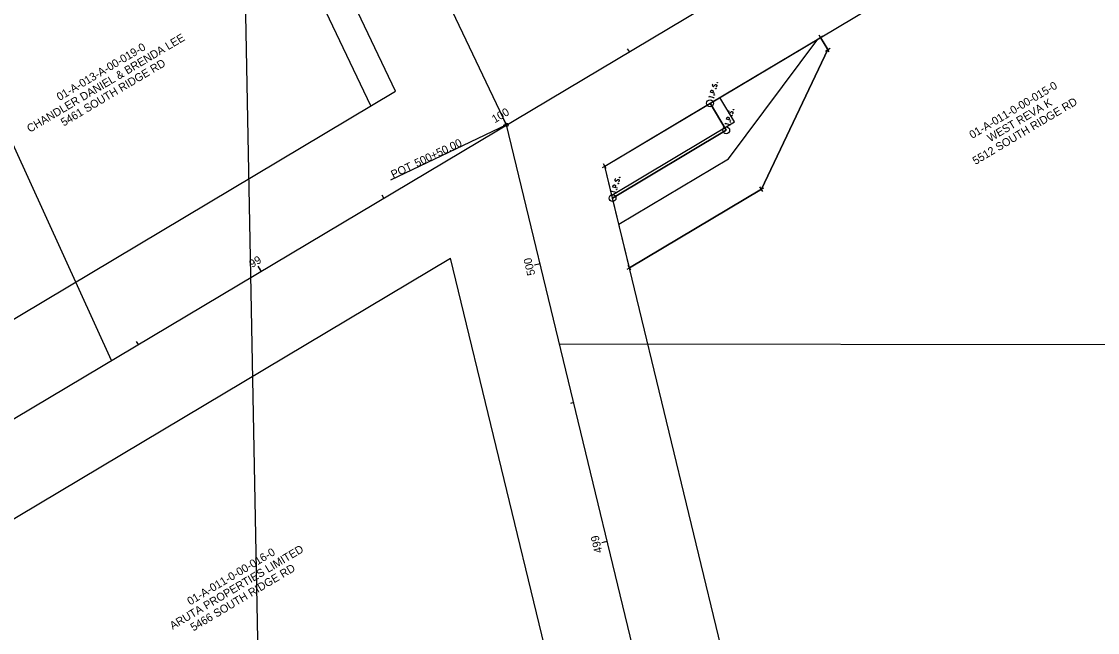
# Model space of a CAD drawing. Extents: x 2351593 to 2354159, y 766293 to 768001.
# Drawn here: x 2352246.2 to 2352622.6, y 766753.2 to 766967.1 of the extents above; entities that cross this region are included whole.
import ezdxf

# ---------------------------------------------------------------- set-up
doc = ezdxf.new("R2010")
doc.units = 0
for name, color, linetype in [('DV_X_Property_Line', 7, 'Continuous'), ('DV_X_Section_VMS_Line', 7, 'Continuous'), ('PTS_ANNO', 7, 'Continuous'), ('RW_P_Easement_Area', 7, 'Continuous'), ('RW_P_Esmt_SH', 7, 'Continuous'), ('RW_P_Esmt_TMP', 7, 'Continuous'), ('RW_P_Taking_Area', 7, 'Continuous'), ('RW_X_CL_100_Cardinal_Points', 7, 'Continuous'), ('RW_X_CL_500_Cardinal_Points', 7, 'Continuous'), ('RW_X_CL_500_Stations', 7, 'Continuous'), ('RW_X_Esmt_U', 7, 'Continuous'), ('SC_Scratch1', 7, 'Continuous'), ('SC_Scratch2', 7, 'Continuous'), ('SC_Scratch3', 7, 'Continuous'), ('SC_Scratch4', 7, 'Continuous'), ('SV_P_Control_Cells_Set', 7, 'Continuous'), ('SV_P_Mon_Cells_Set', 7, 'Continuous'), ('V-SURV-PARL-LINE', 7, 'Continuous'), ('V-SURV-RWAY-CNTR', 7, 'Continuous')]:
    doc.layers.add(name, color=color, linetype=linetype)

msp = doc.modelspace()

# ---------------------------------------------------------------- linework, layer by layer
at = {"layer": 'DV_X_Property_Line'}
for p, q in [((2352277.6, 766848.4), (2352192.4, 767035.46)), ((2352434.4, 766854.25), (2352921.95, 766853.61))]:
    msp.add_line(p, q, dxfattribs=at)
at = {"layer": 'DV_X_Section_VMS_Line'}
msp.add_line((2352337.69, 766292.88), (2352321.61, 767128.88), dxfattribs=at)
at = {"layer": 'PTS_ANNO'}
for p, q in [((2352450.22, 766916.47), (2354158.95, 767936.09)), ((2352377.03, 766942.67), (2352291.74, 767121.83)), ((2351599.99, 766478.99), (2352377.03, 766942.67)), ((2352567.24, 766432.73), (2352450.22, 766916.47)), ((2352570.31, 766420.05), (2352450.22, 766916.47)), ((2351632.95, 766428.79), (2352396.27, 766884.28)), ((2352508.92, 766418.63), (2352396.27, 766884.28))]:
    msp.add_line(p, q, dxfattribs=at)
at = {"layer": 'RW_P_Easement_Area'}
for p, q in [((2352487.05, 766938.44), (2352525.69, 766961.5)), ((2352525.69, 766961.5), (2352528.26, 766957.21)), ((2352528.26, 766957.21), (2352504.98, 766908.39)), ((2352492.69, 766929), (2352487.05, 766938.44)), ((2352452.93, 766905.27), (2352492.69, 766929)), ((2352504.98, 766908.39), (2352458.84, 766880.85)), ((2352458.84, 766880.85), (2352452.93, 766905.27))]:
    msp.add_line(p, q, dxfattribs=at)
at = {"layer": 'RW_P_Esmt_SH'}
for p, q in [((2352492.69, 766929), (2352487.05, 766938.44)), ((2352452.93, 766905.27), (2352492.69, 766929))]:
    msp.add_line(p, q, dxfattribs=at)
at = {"layer": 'RW_P_Esmt_TMP'}
for p, q in [((2352528.26, 766957.21), (2352525.69, 766961.5)), ((2352504.98, 766908.39), (2352528.26, 766957.21)), ((2352458.83, 766880.85), (2352504.98, 766908.39))]:
    msp.add_line(p, q, dxfattribs=at)
at = {"layer": 'RW_P_Taking_Area'}
for p, q in [((2352450.22, 766916.47), (2352487.05, 766938.44)), ((2352487.05, 766938.44), (2352492.69, 766929)), ((2352492.69, 766929), (2352452.93, 766905.27)), ((2352452.93, 766905.27), (2352450.22, 766916.47))]:
    msp.add_line(p, q, dxfattribs=at)
at = {"layer": 'RW_X_CL_100_Cardinal_Points'}
msp.add_line((2352415.86, 766930.9), (2352375.23, 766911.56), dxfattribs=at)
msp.add_circle((2352415.86, 766930.9), 0.6, dxfattribs=at)
at = {"layer": 'RW_X_CL_500_Cardinal_Points'}
msp.add_line((2352415.86, 766930.9), (2352375.23, 766911.56), dxfattribs=at)
msp.add_circle((2352415.86, 766930.9), 0.6, dxfattribs=at)
at = {"layer": 'RW_X_CL_500_Stations'}
for p, q in [((2352415.86, 766930.9), (2352414.84, 766932.62)), ((2352427.62, 766882.3), (2352425.67, 766881.83)), ((2352329.99, 766879.66), (2352329.37, 766880.69)), ((2352451.13, 766785.11), (2352449.96, 766784.82))]:
    msp.add_line(p, q, dxfattribs=at)
at = {"layer": 'RW_X_Esmt_U'}
for p, q in [((2352368.41, 766937.52), (2352281.78, 767119.48)), ((2352493.5, 766919), (2352524.71, 766960.92)), ((2352455.14, 766896.11), (2352493.5, 766919))]:
    msp.add_line(p, q, dxfattribs=at)
at = {"layer": 'SC_Scratch2'}
msp.add_lwpolyline([(2352450.22, 766916.47), (2352487.05, 766938.44), (2352492.69, 766929), (2352452.93, 766905.27)], close=True, dxfattribs=at)
at = {"layer": 'SC_Scratch3'}
msp.add_lwpolyline([(2352487.05, 766938.44), (2352525.69, 766961.5), (2352528.26, 766957.21), (2352504.98, 766908.39), (2352458.83, 766880.85), (2352452.93, 766905.27), (2352492.69, 766929)], close=True, dxfattribs=at)
at = {"layer": 'SC_Scratch4'}
for p, q in [((2352495.61, 766931.91), (2352490.49, 766940.49)), ((2352452.68, 766906.29), (2352495.61, 766931.91))]:
    msp.add_line(p, q, dxfattribs=at)
at = {"layer": 'SV_P_Control_Cells_Set'}
for p, q in [((2352524.88, 766961.02), (2352526.5, 766961.99)), ((2352526.18, 766960.69), (2352525.21, 766962.31)), ((2352527.45, 766956.73), (2352529.07, 766957.69)), ((2352528.74, 766956.4), (2352527.77, 766958.02)), ((2352449.41, 766915.98), (2352451.03, 766916.95)), ((2352450.7, 766915.66), (2352449.73, 766917.28)), ((2352504.17, 766907.91), (2352505.8, 766908.87)), ((2352505.47, 766907.58), (2352504.5, 766909.2)), ((2352459.32, 766880.04), (2352458.35, 766881.66)), ((2352458.03, 766880.37), (2352459.65, 766881.33))]:
    msp.add_line(p, q, dxfattribs=at)
at = {"layer": 'SV_P_Mon_Cells_Set'}
for points in [[(2352489.47, 766945.66), (2352489.49, 766945.71), (2352489.52, 766945.74), (2352489.58, 766945.76), (2352489.64, 766945.74), (2352489.68, 766945.7), (2352489.7, 766945.66), (2352489.68, 766945.6), (2352489.65, 766945.58), (2352489.59, 766945.56), (2352489.53, 766945.57), (2352489.49, 766945.62), (2352489.47, 766945.66)], [(2352488.75, 766941.9), (2352487.19, 766942.29), (2352487.32, 766942.8), (2352487.35, 766942.85), (2352487.39, 766942.92), (2352487.43, 766942.95), (2352487.46, 766942.97), (2352487.53, 766943), (2352487.6, 766943.02), (2352487.7, 766943.01), (2352487.85, 766942.97), (2352487.89, 766942.95), (2352487.96, 766942.91), (2352488.04, 766942.85), (2352488.06, 766942.8), (2352488.08, 766942.76), (2352488.09, 766942.7), (2352488.08, 766942.61), (2352487.95, 766942.1)], [(2352488.04, 766945.18), (2352488.01, 766945.16), (2352487.98, 766945.14), (2352487.92, 766945.05), (2352487.86, 766944.94), (2352487.84, 766944.85), (2352487.83, 766944.82), (2352487.84, 766944.67), (2352487.88, 766944.54), (2352487.96, 766944.44), (2352488.05, 766944.39), (2352488.12, 766944.37), (2352488.23, 766944.37), (2352488.33, 766944.43), (2352488.85, 766944.93), (2352488.91, 766944.97), (2352488.96, 766944.98), (2352489.04, 766944.98), (2352489.12, 766944.96), (2352489.19, 766944.93), (2352489.23, 766944.91), (2352489.29, 766944.87), (2352489.33, 766944.84), (2352489.36, 766944.81), (2352489.39, 766944.77), (2352489.41, 766944.73), (2352489.42, 766944.68), (2352489.43, 766944.65), (2352489.41, 766944.55), (2352489.38, 766944.4), (2352489.33, 766944.31), (2352489.21, 766944.19), (2352489.11, 766944.12)], [(2352488.94, 766943.54), (2352488.95, 766943.59), (2352488.99, 766943.62), (2352489.04, 766943.64), (2352489.1, 766943.62), (2352489.14, 766943.58), (2352489.16, 766943.54), (2352489.15, 766943.49), (2352489.11, 766943.46), (2352489.06, 766943.44), (2352489, 766943.46), (2352488.96, 766943.5), (2352488.94, 766943.54)], [(2352486.77, 766940.6), (2352486.85, 766940.94)], [(2352488.36, 766940.38), (2352486.81, 766940.77)], [(2352488.32, 766940.21), (2352488.41, 766940.55)], [(2352488.39, 766941.36), (2352488.4, 766941.41), (2352488.44, 766941.44), (2352488.49, 766941.46), (2352488.55, 766941.44), (2352488.59, 766941.4), (2352488.61, 766941.36), (2352488.6, 766941.31), (2352488.56, 766941.28), (2352488.51, 766941.26), (2352488.45, 766941.28), (2352488.41, 766941.32), (2352488.39, 766941.36)], [(2352493.68, 766935.73), (2352493.65, 766935.72), (2352493.62, 766935.69), (2352493.55, 766935.6), (2352493.5, 766935.49), (2352493.48, 766935.41), (2352493.47, 766935.37), (2352493.47, 766935.23), (2352493.52, 766935.09), (2352493.59, 766934.99), (2352493.69, 766934.94), (2352493.76, 766934.93), (2352493.86, 766934.92), (2352493.97, 766934.99), (2352494.48, 766935.48), (2352494.55, 766935.52), (2352494.6, 766935.53), (2352494.68, 766935.53), (2352494.75, 766935.52), (2352494.82, 766935.49), (2352494.87, 766935.46), (2352494.93, 766935.43), (2352494.97, 766935.39), (2352495, 766935.36), (2352495.03, 766935.32), (2352495.05, 766935.28), (2352495.06, 766935.23), (2352495.06, 766935.2), (2352495.05, 766935.1), (2352495.01, 766934.95), (2352494.96, 766934.86), (2352494.84, 766934.74), (2352494.75, 766934.68)], [(2352495.11, 766936.21), (2352495.12, 766936.26), (2352495.16, 766936.29), (2352495.21, 766936.31), (2352495.27, 766936.29), (2352495.32, 766936.25), (2352495.33, 766936.21), (2352495.32, 766936.16), (2352495.29, 766936.13), (2352495.23, 766936.11), (2352495.17, 766936.13), (2352495.13, 766936.17), (2352495.11, 766936.21)], [(2352492.4, 766931.15), (2352492.49, 766931.49)], [(2352494, 766930.93), (2352492.45, 766931.32)], [(2352494.38, 766932.45), (2352492.83, 766932.84), (2352492.96, 766933.35), (2352492.99, 766933.4), (2352493.03, 766933.47), (2352493.06, 766933.5), (2352493.09, 766933.53), (2352493.17, 766933.55), (2352493.24, 766933.57), (2352493.34, 766933.57), (2352493.49, 766933.53), (2352493.53, 766933.51), (2352493.6, 766933.47), (2352493.67, 766933.4), (2352493.7, 766933.35), (2352493.72, 766933.31), (2352493.73, 766933.25), (2352493.72, 766933.16), (2352493.59, 766932.65)], [(2352493.96, 766930.76), (2352494.04, 766931.1)], [(2352494.03, 766931.91), (2352494.04, 766931.97), (2352494.07, 766931.99), (2352494.13, 766932.01), (2352494.19, 766932), (2352494.23, 766931.95), (2352494.25, 766931.92), (2352494.23, 766931.86), (2352494.2, 766931.84), (2352494.14, 766931.82), (2352494.08, 766931.83), (2352494.04, 766931.88), (2352494.03, 766931.91)], [(2352494.58, 766934.09), (2352494.59, 766934.15), (2352494.62, 766934.17), (2352494.68, 766934.19), (2352494.74, 766934.18), (2352494.78, 766934.13), (2352494.8, 766934.1), (2352494.78, 766934.04), (2352494.75, 766934.02), (2352494.69, 766934), (2352494.63, 766934.01), (2352494.59, 766934.06), (2352494.58, 766934.09)], [(2352453.92, 766912), (2352453.89, 766911.99), (2352453.85, 766911.96), (2352453.79, 766911.88), (2352453.74, 766911.77), (2352453.72, 766911.68), (2352453.71, 766911.65), (2352453.71, 766911.5), (2352453.75, 766911.36), (2352453.83, 766911.26), (2352453.92, 766911.22), (2352454, 766911.2), (2352454.1, 766911.2), (2352454.21, 766911.26), (2352454.72, 766911.76), (2352454.79, 766911.8), (2352454.84, 766911.81), (2352454.92, 766911.81), (2352454.99, 766911.79), (2352455.06, 766911.76), (2352455.11, 766911.74), (2352455.16, 766911.7), (2352455.21, 766911.67), (2352455.24, 766911.64), (2352455.27, 766911.6), (2352455.28, 766911.56), (2352455.3, 766911.51), (2352455.3, 766911.47), (2352455.29, 766911.37), (2352455.25, 766911.22), (2352455.2, 766911.13), (2352455.08, 766911.02), (2352454.99, 766910.95)], [(2352455.35, 766912.48), (2352455.36, 766912.54), (2352455.39, 766912.56), (2352455.45, 766912.58), (2352455.51, 766912.57), (2352455.55, 766912.52), (2352455.57, 766912.49), (2352455.56, 766912.43), (2352455.52, 766912.41), (2352455.47, 766912.39), (2352455.41, 766912.4), (2352455.37, 766912.45), (2352455.35, 766912.48)], [(2352454.62, 766908.72), (2352453.07, 766909.11), (2352453.2, 766909.63), (2352453.22, 766909.68), (2352453.27, 766909.75), (2352453.3, 766909.77), (2352453.33, 766909.8), (2352453.4, 766909.83), (2352453.47, 766909.84), (2352453.58, 766909.84), (2352453.72, 766909.8), (2352453.77, 766909.78), (2352453.84, 766909.74), (2352453.91, 766909.68), (2352453.94, 766909.62), (2352453.95, 766909.58), (2352453.96, 766909.53), (2352453.96, 766909.44), (2352453.83, 766908.92)], [(2352454.26, 766908.19), (2352454.28, 766908.24), (2352454.31, 766908.27), (2352454.37, 766908.29), (2352454.43, 766908.27), (2352454.47, 766908.23), (2352454.48, 766908.19), (2352454.47, 766908.14), (2352454.44, 766908.11), (2352454.38, 766908.09), (2352454.32, 766908.11), (2352454.28, 766908.15), (2352454.26, 766908.19)], [(2352454.81, 766910.37), (2352454.83, 766910.42), (2352454.86, 766910.45), (2352454.92, 766910.47), (2352454.98, 766910.45), (2352455.02, 766910.41), (2352455.04, 766910.37), (2352455.02, 766910.32), (2352454.99, 766910.29), (2352454.93, 766910.27), (2352454.87, 766910.29), (2352454.83, 766910.33), (2352454.81, 766910.37)], [(2352452.64, 766907.43), (2352452.73, 766907.77)], [(2352454.24, 766907.21), (2352452.69, 766907.6)], [(2352454.19, 766907.03), (2352454.28, 766907.38)]]:
    msp.add_lwpolyline(points, dxfattribs=at)
for centre in [(2352487.05, 766938.44), (2352492.69, 766929), (2352452.93, 766905.27)]:
    msp.add_circle(centre, 1.2, dxfattribs=at)
at = {"layer": 'V-SURV-PARL-LINE'}
for p, q in [((2352458.8, 766956.52), (2352458.18, 766957.55)), ((2352415.86, 766930.9), (2352414.69, 766930.62)), ((2352415.86, 766930.9), (2352414.84, 766932.62)), ((2352372.92, 766905.28), (2352372.31, 766906.31)), ((2352427.62, 766882.3), (2352425.67, 766881.83)), ((2352329.99, 766879.66), (2352328.96, 766881.38)), ((2352287.05, 766854.04), (2352286.43, 766855.07)), ((2352439.37, 766833.7), (2352438.21, 766833.42)), ((2352451.13, 766785.11), (2352449.19, 766784.64))]:
    msp.add_line(p, q, dxfattribs=at)
at = {"layer": 'V-SURV-RWAY-CNTR'}
for p, q in [((2351616.47, 766453.89), (2354143.58, 767961.85)), ((2352415.86, 766930.9), (2352321.61, 767128.88)), ((2352538.08, 766425.68), (2352415.86, 766930.9))]:
    msp.add_line(p, q, dxfattribs=at)

# ---------------------------------------------------------------- texts
at = {"layer": 'RW_X_CL_100_Cardinal_Points'}
for s, p in [('500+50.00', (2352384.46, 766916.01)), ('POT', (2352376.22, 766912.08))]:
    msp.add_text(s, height=2.8, rotation=25.4572, dxfattribs=at).set_placement(p)
at = {"layer": 'RW_X_CL_500_Cardinal_Points'}
for s, p in [('500+50.00', (2352384.46, 766916.01)), ('POT', (2352376.22, 766912.08))]:
    msp.add_text(s, height=2.8, rotation=25.4572, dxfattribs=at).set_placement(p)
at = {"layer": 'RW_X_CL_500_Stations'}
for s, rotation, p in [('100', 30.825, (2352411.74, 766931.41)), ('500', 103.5994, (2352425.91, 766878.51))]:
    msp.add_text(s, height=2.8, rotation=rotation, dxfattribs=at).set_placement(p)
at = {"layer": 'SC_Scratch1'}
for s, p in [('CHANDLER DANIEL & BRENDA LEE', (2352249.09, 766928.1)), ('01-A-013-A-00-019-0', (2352259.51, 766939.21)), ('5461 SOUTH RIDGE RD', (2352260.95, 766930.28)), ('01-A-011-0-00-015-0', (2352578.76, 766925.93)), ('5512 SOUTH RIDGE RD', (2352579.89, 766916.82)), ('WEST REVA K', (2352585.03, 766924.78)), ('ARUTA PROPERTIES LIMITED', (2352299.05, 766754.13)), ('01-A-011-0-00-016-0', (2352305.17, 766762.67)), ('5466 SOUTH RIDGE RD', (2352306.31, 766753.57))]:
    msp.add_text(s, height=2.8, rotation=30.825, dxfattribs=at).set_placement(p)
at = {"layer": 'V-SURV-PARL-LINE'}
for s, rotation, p in [('100', 30.825, (2352411.74, 766931.41)), ('99', 30.825, (2352326.82, 766880.74)), ('500', 103.5994, (2352425.91, 766878.51)), ('499', 103.5994, (2352449.42, 766781.35))]:
    msp.add_text(s, height=2.8, rotation=rotation, dxfattribs=at).set_placement(p)

doc.saveas('drawing.dxf')
